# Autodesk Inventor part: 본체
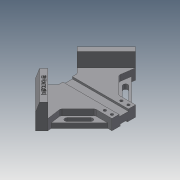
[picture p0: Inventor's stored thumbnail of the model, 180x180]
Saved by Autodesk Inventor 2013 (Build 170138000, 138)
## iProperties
Created: 2020-05
Part Number: 본체
Material: Generic
Document SubType Name: Modeling
Designer: user
Density: 1 g/cm^3
Author: user
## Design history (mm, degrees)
sketch "스케치2"
  geometry: L1 (-84.853, 0)-(0, 84.853); L2 (0, 84.853)-(84.853, 0); L3 (84.853, 0)-(0, -84.853); L4 (0, -84.853)-(-84.853, 0); 1 further point
  constraints: 8 end point, 2 horizontal alignment, 2 parallel, 1 vertical alignment
  dimensions: "d5" = 120 distance of L3.end L1.start; "d7" = 120 distance of L2.end L3.end; "d8" = 90 deg angle of L4 L1
extrude "돌출1" new body sketch "스케치2" distance "d9" = 18; taper "d10" = 0 deg
sketch "스케치3"
  geometry: L1 (84.853, 0)-(0, 84.853) reference; L2 (0, 84.853)-(35.355, 49.497); L3 (35.355, 49.497)-(0, 14.142); L4 (0, 14.142)-(-35.355, 49.497); L5 (-35.355, 49.497)-(0, 84.853); 1 further point
  constraints: 8 end point, 2 parallel, 1 perpendicular, 1 point on line
  dimensions: "d11" = 50 distance of L2.end L3.end; "d12" = 50 distance of L1.end L2.end
extrude "돌출2" cut sketch "스케치3" stored distance "d13" = 18; taper "d14" = 0 deg
sketch "스케치4"
  geometry: L1 (-35.355, 49.497)-(-84.853, 0) reference; L2 (84.853, 0)-(35.355, 49.497) reference; L3 (-84.853, 0)-(-35.355, 49.497); L4 (-35.355, 49.497)-(-24.749, 38.891); L5 (-24.749, 38.891)-(-74.246, -10.607); L6 (-74.246, -10.607)-(-84.853, 0); L7 (84.853, 0)-(35.355, 49.497); L8 (35.355, 49.497)-(24.749, 38.891); L9 (24.749, 38.891)-(74.246, -10.607); L10 (74.246, -10.607)-(84.853, 0); 1 further point
  constraints: 16 end point, 6 equal length, 2 perpendicular
  dimensions: "d15" = 15 distance of L1.start L4.end; "d16" = 15 distance of L8.end L2.end
extrude "돌출3" join sketch "스케치4" distance "d17" = 24; taper "d18" = 0 deg
sketch "스케치5"
  geometry: L1 (0, -84.853)-(0, 10.147); L2 (20, -84.853)-(20, -64.853); L3 (-20, -84.853)-(-20, -64.853); L4 (-20, -84.853)-(20, -84.853); L5 (-20, -64.853)-(20, -64.853); 1 further point
  constraints: 10 end point, 3 parallel, 1 midpoint, 1 perpendicular, 1 vertical
  dimensions: "d19" = 95 distance of L1.start L1.end; "d20" = 40 distance of L3.start L2.start; "d21" = 20 distance between parallel lines of L4 L5
extrude "돌출4" cut sketch "스케치5" stored distance "d22" = 24; taper "d23" = 0 deg
sketch "스케치6"
  geometry: L1 (-20, -64.853)-(20, -64.853) reference; L2 (24.749, 38.891)-(0, 14.142) reference; L3 (0, 14.142)-(-24.749, 38.891) reference; L4 (0, -64.853)-(0, 30.147); L5 (0, 30.147)-(-16.005, 30.147); L6 (-16.005, 30.147)-(-16.005, 14.142); L7 (0, 30.147)-(16.005, 30.147); L8 (16.005, 30.147)-(16.005, 14.142); L9 (0, 14.142)-(16.005, 14.142); L10 (0, 14.142)-(-16.005, 14.142); 1 further point
  constraints: 14 end point, 3 perpendicular, 2 point on line, 1 midpoint
  dimensions: "d24" = 95 distance of L4.start L4.end; "d25" = 16.00505 distance of L4.end L7.end; "d26" = 16.00505 distance of L7.end L8.end; "d27" = 16.00505 distance of L2.end L6.end; "d28" = 16.00505 distance of L2.end L8.end
extrude "돌출5" join sketch "스케치6" distance "d29" = 18; taper "d30" = 0 deg
sketch "스케치7"
  geometry: L1 (-20, -64.853)-(20, -64.853) reference; L2 (16.005, 30.147)-(-16.005, 30.147) reference; L3 (0, -64.853)-(0, 30.147); L4 (8, -64.853)-(8, 30.147); L5 (-8, -64.853)-(-8, 30.147); L6 (-8, 30.147)-(8, 30.147); L7 (8, -64.853)-(-8, -64.853); 2 further points
  constraints: 10 end point, 4 midpoint, 2 parallel, 1 collinear, 1 perpendicular
  dimensions: "d31" = 16 distance of L5.end L4.end; "d33" = 95 distance of L4.start L4.end
extrude "돌출6" cut sketch "스케치7" distance "d34" = 3.5; taper "d35" = 0 deg
sketch "스케치8"
  geometry: L1 (20, 64.853)-(-20, 64.853) reference; L2 (-16.005, -30.147)-(16.005, -30.147) reference; L3 (0, -30.147)-(0, 64.853); L4 (6, -30.147)-(6, 64.853); L5 (-6, -30.147)-(-6, 64.853); L6 (-6, 64.853)-(6, 64.853); L7 (6, -30.147)-(-6, -30.147); 2 further points
  constraints: 10 end point, 4 midpoint, 2 parallel, 1 perpendicular
  dimensions: "d36" = 12 distance between parallel lines of L4 L5; "d38" = 95 distance of L4.start L4.end; "d39" = 95 distance of L5.start L5.end
extrude "돌출7" cut sketch "스케치8" distance "d40" = 3; taper "d41" = 0 deg
sketch "스케치11"
  geometry: L1 (20, 64.853)-(6, 64.853) reference; L2 (-6, 64.853)-(-20, 64.853) reference; 5 further points
  constraints: 2 vertical alignment
  dimensions: "d50" = 28 distance of point (14, 58.853) point (-14, 58.853); "d52" = 6 distance from line of L2 point (-14, 58.853); "d53" = 6 distance from line of point (14, 58.853) L1; "d54" = 12 distance of point (14, 58.853) point (14, 46.853); "d55" = 12 distance of point (-14, 58.853) point (-14, 46.853); "d56" = 14 horizontal distance of point (-14, 58.853) point (0, 0)
hole "구멍1" sketch "스케치11" at (-14, 58.853), (-14, 46.853), (14, 58.853), (14, 46.853) diameter "d57" = 4.5; stored, may be unused: countersink angle "d61" = 90 deg, drill point angle "d63" = 118 deg; dims "d58" = 6, "d59" = 8, "d60" = 10, "d62" = 8
sketch "스케치12"
  geometry: L1 (-74.246, -10.607)-(-20, -64.853) reference; L2 (-20, -64.853)-(-8, -64.853) reference; L3 (-20, -64.853)-(-20, -36.569); L4 (-20, -36.569)-(-49.497, -7.071); L5 (-49.497, -7.071)-(-74.246, -10.607); L6 (-35.355, 49.497)-(-84.853, 0) reference; L7 (-74.246, -10.607)-(-20, -64.853); 1 further point
  constraints: 8 end point, 2 perpendicular, 1 parallel
  dimensions: "d64" = 20 distance from line of L1 L4.end; "d65" = 30 distance from line of L6 L4.end
extrude "돌출8" cut sketch "스케치12" distance "d66" = 10; taper "d67" = 0 deg
sketch "스케치13"
  geometry: L1 (-20, -64.853)-(-74.246, -10.607) reference; L2 (-20, -36.569)-(-20, -64.853) reference; L3 (-49.497, -7.071)-(-20, -36.569) reference; L4 (-74.246, -10.607)-(-49.497, -7.071) reference; L5 (-68.059, -9.723)-(-20, -57.782); L6 (-68.059, -9.723)-(-74.246, -10.607); L7 (-20, -64.853)-(-20, -57.782); L8 (-20, -64.853)-(-74.246, -10.607); 1 further point
  constraints: 8 end point, 2 collinear, 2 point on line, 1 parallel
  dimensions: "d68" = 5 distance between parallel lines of L1 L5
extrude "돌출9" cut sketch "스케치13" stored distance "d69" = 10; taper "d70" = 0 deg
sketch "스케치14"
  geometry: L1 (-49.497, -7.071)-(-20, -36.569) reference; L2 (-52.326, -21.213)-(-46.669, -15.556); L3 (-46.669, -15.556)-(-26.87, -35.355); L4 (-26.87, -35.355)-(-32.527, -41.012); L5 (-32.527, -41.012)-(-52.326, -21.213); L6 (-35.355, 49.497)-(-84.853, 0) reference; L7 (-84.853, 0)-(-74.246, -10.607) reference; C1 r 4 at (-29.698, -38.184); A1 r 4 centre (-49.497, -18.385) between (-52.326, -21.213) and (-46.669, -15.556); 2 further points
  constraints: 8 end point, 2 centre point, 2 parallel, 2 perpendicular, 2 point on circle, 1 coincident, 1 midpoint
  dimensions: "d71" = 8 diameter of A1; "d72" = 8 diameter of C1; "d73" = 8 distance of L2.start L2.end; "d74" = 38 distance from line of L6 A1.centre; "d75" = 28 distance of C1.centre A1.centre; "d91" = 12 distance from line of L7 A1.centre
extrude "돌출10" cut sketch "스케치14" stored distance "d77" = 10; taper "d78" = 0 deg
chamfer "모따기1" distance "d79" = 5; stored, may be unused: second distance "d80" = 15, angle "d81" = 45 deg
chamfer "모따기2" distance "d82" = 5; stored, may be unused: second distance "d83" = 15, angle "d84" = 45 deg
fillet "모깎기1" dims "d85" = 5
fillet "모깎기2" dims "d86" = 5
sketch "스케치16"
  geometry: L1 (-74.246, -10.607)-(-24.749, 38.891) reference; L2 (-24.749, 38.891)-(-31.82, 45.962) reference; 2 further points
  constraints: 1 other
  dimensions: "d87" = 35 distance from line of L2 point (-53.033, 17.678); "d88" = 5 distance from line of L1 point (-53.033, 17.678)
feature "엠보싱1" sketch "스케치16" dims "d7" = 120, "d15" = 15, "d89" = 0.5, "d90" = 0
node "솔리드1"
mirror "대칭1"
